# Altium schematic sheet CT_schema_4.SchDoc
size 362 x 192 mm
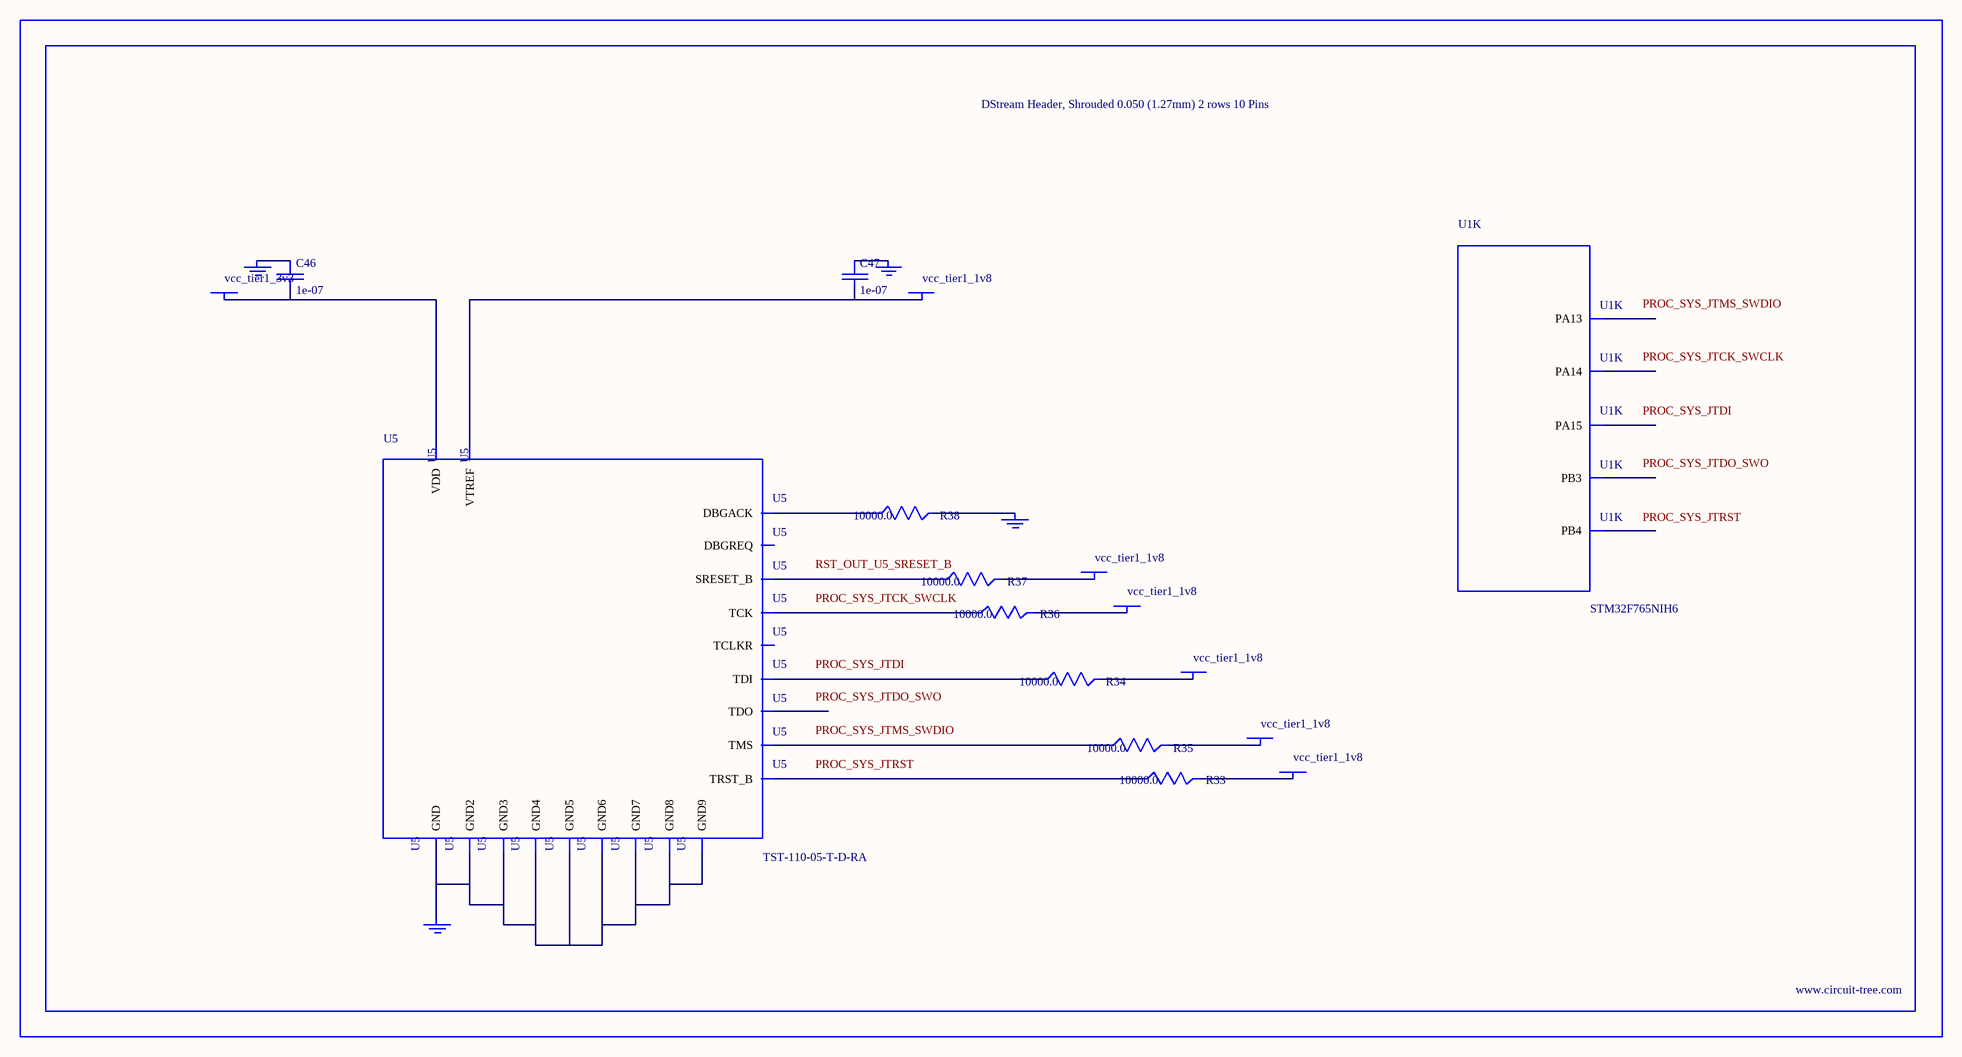
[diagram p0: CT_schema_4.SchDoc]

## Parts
BORDER3  (no value)
C46  1e-07  [C0402]
C47  1e-07  [C0402]
GND_INSTANCE_3_0  (no value)
GND_INSTANCE_3_1  (no value)
GND_INSTANCE_3_2  (no value)
GND_INSTANCE_3_3  (no value)
POWER_INSTANCE_3_0  vcc_tier1_1v8
POWER_INSTANCE_3_1  vcc_tier1_3v3
POWER_INSTANCE_3_2  vcc_tier1_1v8
POWER_INSTANCE_3_3  vcc_tier1_1v8
POWER_INSTANCE_3_4  vcc_tier1_1v8
POWER_INSTANCE_3_5  vcc_tier1_1v8
POWER_INSTANCE_3_6  vcc_tier1_1v8
R33  10000.0  [R0603]
R34  10000.0  [R0603]
R35  10000.0  [R0603]
R36  10000.0  [R0603]
R37  10000.0  [R0603]
R38  10000.0  [R0603]
U1  STM32F765NIH6  [TFBGA216]  (part K of 15)
U5  TST-110-05-T-D-RA  [TST-110-05-T-D-RA]

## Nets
NetC46_1: C46.1 GND_INSTANCE_3_1.0(GND)
NetC46_2: C46.2 POWER_INSTANCE_3_1.0(PWR) U5.2(VDD)
NetC47_1: C47.1 GND_INSTANCE_3_0.0(GND)
NetC47_2: C47.2 POWER_INSTANCE_3_0.0(PWR) U5.1(VTREF)
NetGND_INSTANCE_3_2_0: GND_INSTANCE_3_2.0(GND) R38.2
NetGND_INSTANCE_3_3_0: GND_INSTANCE_3_3.0(GND) U5.4(GND) U5.6(GND2) U5.8(GND3) U5.10(GND4) U5.12(GND5) U5.14(GND6) U5.16(GND7) U5.18(GND8) U5.20(GND9)
NetPOWER_INSTANCE_3_2_0: POWER_INSTANCE_3_2.0(PWR) R33.2
NetPOWER_INSTANCE_3_3_0: POWER_INSTANCE_3_3.0(PWR) R34.2
NetPOWER_INSTANCE_3_4_0: POWER_INSTANCE_3_4.0(PWR) R35.2
NetPOWER_INSTANCE_3_5_0: POWER_INSTANCE_3_5.0(PWR) R36.2
NetPOWER_INSTANCE_3_6_0: POWER_INSTANCE_3_6.0(PWR) R37.2
NetR33_1: R33.1 U5.3(TRST_B)
NetR34_1: R34.1 U5.5(TDI)
NetR35_1: R35.1 U5.7(TMS)
NetR36_1: R36.1 U5.9(TCK)
NetR37_1: R37.1 U5.15(SRESET_B)
NetR38_1: R38.1 U5.19(DBGACK)

Not connected (* = marked no-connect by the designer): U1 A9(PB4) A10(PB3) A13(PA15) A14(PA14) A15(PA13); U5 11(TCLKR) 13(TDO) 17(DBGREQ)

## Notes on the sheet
- Labels drawn without touching a wire or pin: PROC_SYS_JTCK_SWCLK, PROC_SYS_JTDI, PROC_SYS_JTDO_SWO, PROC_SYS_JTMS_SWDIO, PROC_SYS_JTRST, RST_OUT_U5_SRESET_B

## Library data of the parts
BORDER3 = BORDER_PAGE3
C46 C47 = C0402C104K3RACTU
GND_INSTANCE_3_0-GND_INSTANCE_3_3 = GND
POWER_INSTANCE_3_0-POWER_INSTANCE_3_6 = PWR
R33-R38 = RC0603JR-0710KL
